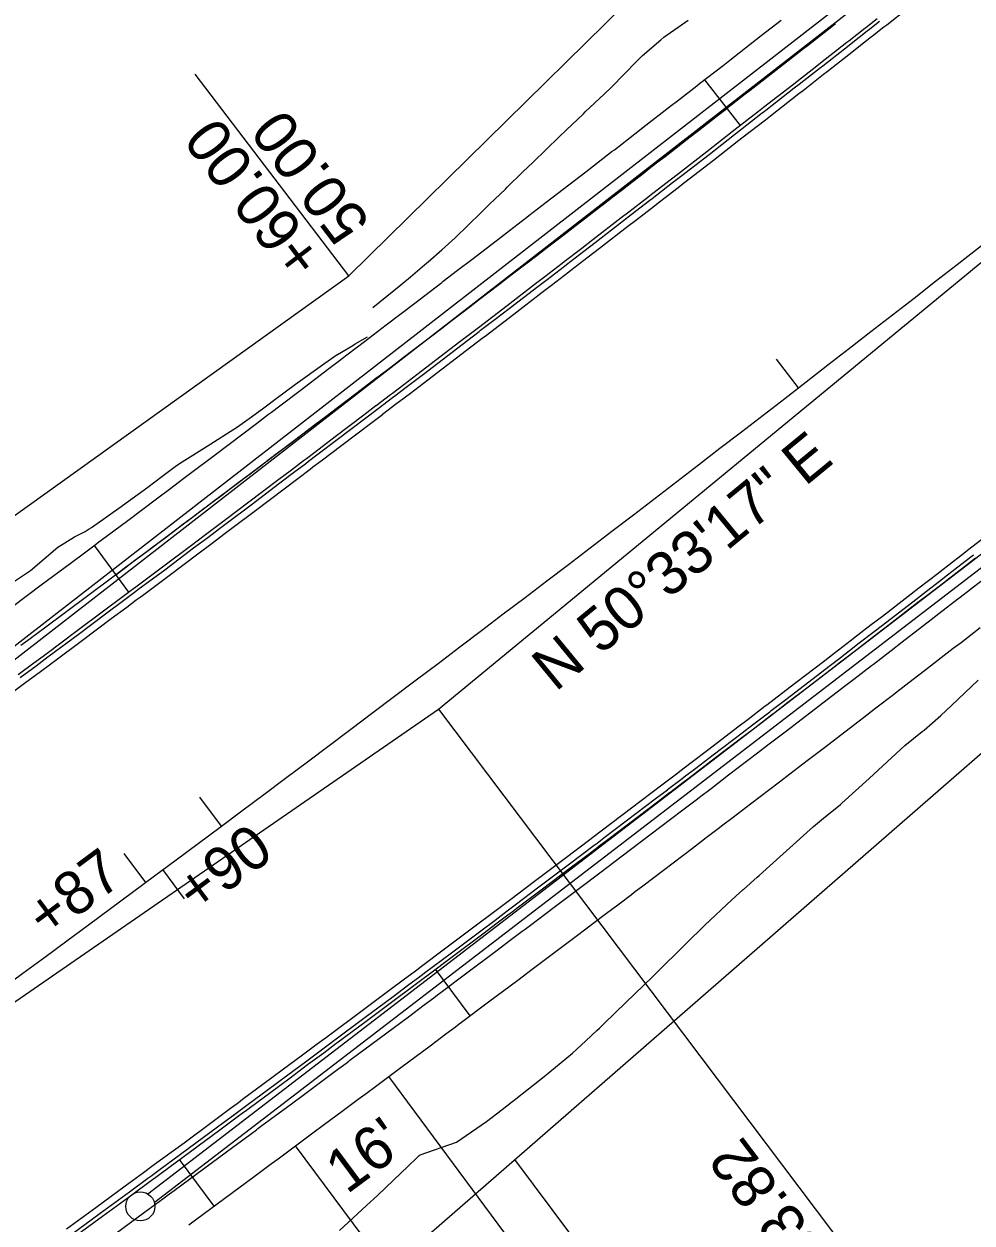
# Model space of a CAD drawing. Extents: x 1147550 to 1149124, y 2017436 to 2018779.
# Drawn here: x 1148434.3 to 1148565.1, y 2018092.6 to 2018257.9 of the extents above; entities that cross this region are included whole.
import ezdxf

# ---------------------------------------------------------------- set-up
doc = ezdxf.new("R2010")
doc.units = 0
for name, color, linetype in [('S_EDGE_CONCRETE', 7, 'Continuous'), ('S_ELECTRIC_UTILITIES', 7, 'Continuous'), ('S_HEADWALL', 7, 'Continuous'), ('S_IRON_PIN', 7, 'Continuous'), ('S_MAILBOX', 7, 'Continuous'), ('S_RDW_PT_SYM', 7, 'Continuous'), ('S_SECONDARY_CTL', 7, 'Continuous'), ('S_TELEPHONE_UTILITIES', 7, 'Continuous'), ('S_TELEPHONE_UTILITIES_ANNOT', 7, 'Continuous')]:
    doc.layers.add(name, color=color, linetype=linetype)

msp = doc.modelspace()

# ---------------------------------------------------------------- linework, layer by layer
at = {"layer": 'S_EDGE_CONCRETE'}
for p, q in [((1148491.47, 2018163.46), (1148677.53, 2018316.54)), ((1148293.22, 2018026.54), (1148491.47, 2018163.46))]:
    msp.add_line(p, q, dxfattribs=at)
for points in [[(1148538.07, 2018211.71), (1148541.13, 2018207.76)], [(1148458.49, 2018151.3), (1148461.48, 2018147.3)]]:
    msp.add_lwpolyline(points, dxfattribs=at)
msp.add_arc((1145037.29, 2022741.09), 5729.58, 304.629463, 309.445337, dxfattribs=at)
at = {"layer": 'S_ELECTRIC_UTILITIES'}
msp.add_lwpolyline([(1148479.1, 2018223.18), (1148457.89, 2018251.02)], dxfattribs=at)
at = {"layer": 'S_HEADWALL'}
for p, q in [((1148528.18, 2018250.22), (1148533.11, 2018243.93)), ((1148443.96, 2018186.01), (1148448.73, 2018179.58)), ((1148448.07, 2018143.55), (1148451.05, 2018139.54)), ((1148456.44, 2018137.31), (1148453.46, 2018141.33)), ((1148495.84, 2018121.16), (1148491.07, 2018127.58)), ((1148503.99, 2018086.7), (1148484.62, 2018112.78)), ((1148491.14, 2018077.16), (1148471.77, 2018103.24)), ((1148460.51, 2018094.93), (1148455.74, 2018101.35))]:
    msp.add_line(p, q, dxfattribs=at)
at = {"layer": 'S_IRON_PIN'}
msp.add_line((1148509.76, 2018090.99), (1148502.03, 2018101.35), dxfattribs=at)
at = {"layer": 'S_MAILBOX'}
for points in [[(1147550.1, 2017525.89), (1147894.72, 2017801.4), (1147903.55, 2017831.14), (1148035.64, 2017933.4), (1148261.5, 2018084.85), (1148285.74, 2018084.65), (1148479.1, 2018223.18), (1148835.76, 2018573.62)], [(1147623.68, 2017436.42), (1147751.67, 2017548.43), (1147958.55, 2017704.02), (1148020.45, 2017753.36), (1148124.6, 2017828.73), (1148174.25, 2017853.51), (1148282.74, 2017941.53), (1148421.63, 2018031.39), (1148612.18, 2018197.22), (1148639.91, 2018214.06), (1148753.45, 2018306.48), (1148799.03, 2018350.69)]]:
    msp.add_lwpolyline(points, dxfattribs=at)
at = {"layer": 'S_RDW_PT_SYM'}
msp.add_lwpolyline([(1148491.47, 2018163.46), (1148563.75, 2018067.67)], dxfattribs=at)
at = {"layer": 'S_SECONDARY_CTL'}
for points in [[(1148482.43, 2018218.81), (1148486.27, 2018221.95), (1148487.63, 2018223.07), (1148489.88, 2018224.99), (1148490.07, 2018225.15), (1148491.95, 2018226.8), (1148493.79, 2018228.45), (1148497.37, 2018231.94), (1148498.52, 2018233.07), (1148500.71, 2018235.17), (1148500.95, 2018235.41), (1148503.14, 2018237.52), (1148504.54, 2018238.87), (1148508.13, 2018242.35), (1148509.08, 2018243.28), (1148511.47, 2018245.54), (1148511.73, 2018245.79), (1148514.34, 2018248.24), (1148515.35, 2018249.22), (1148518.86, 2018252.79), (1148519.64, 2018253.59), (1148522.17, 2018255.76), (1148522.57, 2018256.09), (1148525.92, 2018258.43)], [(1148431.06, 2018179.8), (1148435.18, 2018182.58), (1148438.97, 2018185.79), (1148441.26, 2018187.2), (1148442.72, 2018187.96), (1148443.29, 2018188.31), (1148443.61, 2018188.5), (1148447.36, 2018191.14), (1148451.36, 2018194.08), (1148453.32, 2018195.54), (1148454.96, 2018196.75), (1148455.35, 2018197.04), (1148456.1, 2018197.53), (1148459.55, 2018199.71), (1148463.75, 2018202.38), (1148465.68, 2018203.75), (1148467.37, 2018205), (1148467.77, 2018205.29), (1148468.92, 2018206.14), (1148471.76, 2018208.24), (1148475.78, 2018211.16), (1148477.5, 2018212.33), (1148477.54, 2018212.35), (1148479.68, 2018213.61), (1148480, 2018213.8), (1148481.71, 2018214.8)], [(1148477.83, 2018091.58), (1148481.57, 2018095.01), (1148483.05, 2018096.4), (1148485.27, 2018098.5), (1148487.28, 2018100.41), (1148488.43, 2018101.52), (1148488.82, 2018101.9), (1148488.94, 2018102.01), (1148493.96, 2018103.72), (1148498.12, 2018106.58), (1148500.27, 2018108.26), (1148501.57, 2018109.27), (1148502.1, 2018109.69), (1148502.4, 2018109.92), (1148506.07, 2018112.81), (1148509.98, 2018116.01), (1148511.81, 2018117.72), (1148513.33, 2018119.15), (1148513.68, 2018119.48), (1148514.35, 2018120.12), (1148517.35, 2018123), (1148521, 2018126.55), (1148522.73, 2018128.24), (1148524.27, 2018129.75), (1148524.63, 2018130.11), (1148525.68, 2018131.14), (1148528.25, 2018133.68), (1148531.94, 2018137.17), (1148533.54, 2018138.57), (1148533.57, 2018138.59), (1148535.45, 2018140.27), (1148535.73, 2018140.52), (1148537.22, 2018141.86), (1148539.49, 2018143.9), (1148543.25, 2018147.29), (1148544.63, 2018148.44), (1148546.96, 2018150.32), (1148547.15, 2018150.49), (1148549.04, 2018152.2), (1148550.89, 2018153.89), (1148554.63, 2018157.32), (1148555.84, 2018158.42), (1148558.21, 2018160.35), (1148558.48, 2018160.57), (1148560.82, 2018162.57), (1148562.25, 2018163.94), (1148565.93, 2018167.43)]]:
    msp.add_lwpolyline(points, dxfattribs=at)
at = {"layer": 'S_TELEPHONE_UTILITIES'}
for points in [[(1148431.98, 2018165.24), (1148434.38, 2018167.02), (1148436.56, 2018168.64), (1148437.81, 2018169.57), (1148438.24, 2018169.89), (1148438.37, 2018169.98), (1148442.35, 2018172.95), (1148446.34, 2018175.93), (1148448.49, 2018177.53), (1148449.79, 2018178.5), (1148450.32, 2018178.9), (1148450.62, 2018179.12), (1148454.3, 2018181.88), (1148458.28, 2018184.87), (1148460.24, 2018186.34), (1148461.87, 2018187.57), (1148462.25, 2018187.85), (1148462.98, 2018188.4), (1148466.23, 2018190.84), (1148470.2, 2018193.84), (1148472.09, 2018195.27), (1148473.77, 2018196.54), (1148474.16, 2018196.84), (1148475.31, 2018197.7), (1148478.13, 2018199.84), (1148482.09, 2018202.84), (1148483.75, 2018204.1), (1148483.78, 2018204.13), (1148485.75, 2018205.63), (1148486.05, 2018205.85), (1148487.62, 2018207.04), (1148490, 2018208.86), (1148493.96, 2018211.87), (1148495.36, 2018212.95), (1148497.71, 2018214.74), (1148497.91, 2018214.89), (1148499.9, 2018216.41), (1148501.86, 2018217.91), (1148505.8, 2018220.94), (1148507.08, 2018221.92), (1148509.48, 2018223.76), (1148509.75, 2018223.97), (1148512.15, 2018225.82), (1148513.69, 2018227), (1148517.63, 2018230.04), (1148518.68, 2018230.85), (1148521.27, 2018232.85), (1148521.56, 2018233.07), (1148524.38, 2018235.26), (1148525.49, 2018236.12), (1148529.42, 2018239.16), (1148530.31, 2018239.85), (1148532.94, 2018241.89), (1148533.35, 2018242.21), (1148536.59, 2018244.73), (1148537.28, 2018245.26), (1148541.2, 2018248.32), (1148541.85, 2018248.82), (1148544.61, 2018250.99), (1148545.12, 2018251.38), (1148548.76, 2018254.23), (1148549.03, 2018254.44), (1148551.25, 2018256.18), (1148551.38, 2018256.28), (1148552.95, 2018257.51), (1148553.36, 2018257.83), (1148556.24, 2018260.09)], [(1148432.7, 2018177.6), (1148436.68, 2018180.57), (1148440.66, 2018183.54), (1148442.8, 2018185.14), (1148444.1, 2018186.11), (1148444.63, 2018186.51), (1148444.93, 2018186.73), (1148448.61, 2018189.48), (1148452.58, 2018192.46), (1148454.53, 2018193.93), (1148456.16, 2018195.16), (1148456.54, 2018195.44), (1148457.27, 2018195.99), (1148460.51, 2018198.43), (1148464.47, 2018201.42), (1148466.36, 2018202.85), (1148468.04, 2018204.11), (1148468.43, 2018204.41), (1148469.58, 2018205.28), (1148472.39, 2018207.41), (1148476.35, 2018210.41), (1148478.01, 2018211.67), (1148478.04, 2018211.69), (1148480, 2018213.19), (1148480.3, 2018213.41), (1148481.86, 2018214.6), (1148484.25, 2018216.42), (1148488.2, 2018219.43), (1148489.6, 2018220.5), (1148491.94, 2018222.29), (1148492.14, 2018222.44), (1148494.12, 2018223.96), (1148496.08, 2018225.46), (1148500.02, 2018228.48), (1148501.29, 2018229.45), (1148503.69, 2018231.29), (1148503.96, 2018231.5), (1148506.36, 2018233.35), (1148507.89, 2018234.53), (1148511.82, 2018237.56), (1148512.87, 2018238.37), (1148515.46, 2018240.37), (1148515.75, 2018240.59), (1148518.57, 2018242.77), (1148519.68, 2018243.63), (1148523.6, 2018246.67), (1148524.48, 2018247.35), (1148527.11, 2018249.39), (1148527.52, 2018249.71), (1148530.75, 2018252.22), (1148531.44, 2018252.76), (1148535.36, 2018255.81), (1148536, 2018256.32), (1148538.77, 2018258.47)], [(1148433.48, 2018168.22), (1148435.66, 2018169.84), (1148436.92, 2018170.77), (1148437.34, 2018171.09), (1148437.47, 2018171.19), (1148441.46, 2018174.15), (1148445.44, 2018177.13), (1148447.59, 2018178.73), (1148448.89, 2018179.7), (1148449.42, 2018180.1), (1148449.72, 2018180.33), (1148453.4, 2018183.08), (1148457.38, 2018186.07), (1148459.34, 2018187.54), (1148460.97, 2018188.77), (1148461.35, 2018189.05), (1148462.08, 2018189.6), (1148465.32, 2018192.04), (1148469.29, 2018195.03), (1148471.18, 2018196.46), (1148472.86, 2018197.73), (1148473.26, 2018198.03), (1148474.4, 2018198.9), (1148477.22, 2018201.03), (1148481.18, 2018204.04), (1148482.84, 2018205.3), (1148482.88, 2018205.32), (1148484.85, 2018206.82), (1148485.14, 2018207.04), (1148486.71, 2018208.23), (1148489.1, 2018210.05), (1148493.05, 2018213.07), (1148494.45, 2018214.14), (1148496.8, 2018215.93), (1148497, 2018216.08), (1148498.98, 2018217.6), (1148500.95, 2018219.11), (1148504.89, 2018222.13), (1148506.17, 2018223.11), (1148508.56, 2018224.95), (1148508.83, 2018225.16), (1148511.24, 2018227.01), (1148512.77, 2018228.19), (1148516.71, 2018231.22), (1148517.76, 2018232.03), (1148520.36, 2018234.04), (1148520.64, 2018234.26), (1148523.46, 2018236.44), (1148524.58, 2018237.3), (1148528.5, 2018240.35), (1148529.39, 2018241.03), (1148532.02, 2018243.08), (1148532.43, 2018243.4), (1148535.66, 2018245.91), (1148536.35, 2018246.45), (1148540.28, 2018249.5), (1148540.92, 2018250.01), (1148543.69, 2018252.17), (1148544.19, 2018252.56), (1148547.84, 2018255.41), (1148548.11, 2018255.62), (1148550.32, 2018257.36), (1148550.46, 2018257.46), (1148552.02, 2018258.69)], [(1148433.78, 2018167.82), (1148435.96, 2018169.44), (1148437.22, 2018170.37), (1148437.64, 2018170.69), (1148437.77, 2018170.78), (1148441.76, 2018173.75), (1148445.74, 2018176.73), (1148447.89, 2018178.33), (1148449.19, 2018179.3), (1148449.72, 2018179.7), (1148450.02, 2018179.93), (1148453.7, 2018182.68), (1148457.68, 2018185.67), (1148459.64, 2018187.14), (1148461.27, 2018188.37), (1148461.65, 2018188.65), (1148462.38, 2018189.2), (1148465.63, 2018191.64), (1148469.59, 2018194.64), (1148471.49, 2018196.06), (1148473.17, 2018197.33), (1148473.56, 2018197.63), (1148474.71, 2018198.5), (1148477.52, 2018200.63), (1148481.48, 2018203.64), (1148483.15, 2018204.9), (1148483.18, 2018204.92), (1148485.15, 2018206.42), (1148485.44, 2018206.64), (1148487.01, 2018207.84), (1148489.4, 2018209.66), (1148493.35, 2018212.67), (1148494.76, 2018213.74), (1148497.1, 2018215.54), (1148497.3, 2018215.69), (1148499.29, 2018217.21), (1148501.25, 2018218.71), (1148505.2, 2018221.73), (1148506.47, 2018222.71), (1148508.87, 2018224.55), (1148509.14, 2018224.76), (1148511.54, 2018226.61), (1148513.08, 2018227.79), (1148517.02, 2018230.83), (1148518.07, 2018231.64), (1148520.66, 2018233.64), (1148520.95, 2018233.87), (1148523.77, 2018236.05), (1148524.88, 2018236.91), (1148528.81, 2018239.95), (1148529.69, 2018240.64), (1148532.33, 2018242.68), (1148532.74, 2018243), (1148535.97, 2018245.52), (1148536.66, 2018246.05), (1148540.58, 2018249.11), (1148541.23, 2018249.61), (1148544, 2018251.78), (1148544.5, 2018252.17), (1148548.15, 2018255.02), (1148548.42, 2018255.23), (1148550.63, 2018256.96), (1148550.77, 2018257.07), (1148552.33, 2018258.3)], [(1148433.87, 2018172.25), (1148435.13, 2018173.18), (1148435.55, 2018173.5), (1148435.68, 2018173.59), (1148439.67, 2018176.56), (1148443.65, 2018179.53), (1148445.8, 2018181.14), (1148447.09, 2018182.11), (1148447.63, 2018182.51), (1148447.92, 2018182.73), (1148451.6, 2018185.48), (1148455.58, 2018188.46), (1148457.54, 2018189.93), (1148459.17, 2018191.16), (1148459.55, 2018191.45), (1148460.27, 2018191.99), (1148463.52, 2018194.44), (1148467.49, 2018197.43), (1148469.38, 2018198.86), (1148471.05, 2018200.13), (1148471.45, 2018200.42), (1148472.59, 2018201.29), (1148475.41, 2018203.42), (1148479.37, 2018206.42), (1148481.03, 2018207.69), (1148481.06, 2018207.71), (1148483.03, 2018209.21), (1148483.32, 2018209.43), (1148484.89, 2018210.62), (1148487.28, 2018212.44), (1148491.23, 2018215.45), (1148492.63, 2018216.52), (1148494.98, 2018218.32), (1148495.18, 2018218.47), (1148497.16, 2018219.99), (1148499.12, 2018221.49), (1148503.06, 2018224.51), (1148504.34, 2018225.49), (1148506.73, 2018227.33), (1148507, 2018227.54), (1148509.41, 2018229.38), (1148510.94, 2018230.57), (1148514.88, 2018233.6), (1148515.93, 2018234.41), (1148518.52, 2018236.41), (1148518.81, 2018236.63), (1148521.63, 2018238.81), (1148522.74, 2018239.67), (1148526.67, 2018242.72), (1148527.55, 2018243.4), (1148530.18, 2018245.45), (1148530.59, 2018245.76), (1148533.82, 2018248.28), (1148534.51, 2018248.82), (1148538.43, 2018251.87), (1148539.08, 2018252.37), (1148541.84, 2018254.53), (1148542.35, 2018254.93), (1148545.99, 2018257.77), (1148546.26, 2018257.99)], [(1148440.16, 2018091.77), (1148444.22, 2018094.74), (1148448.27, 2018097.71), (1148450.79, 2018099.56), (1148451.32, 2018099.96), (1148451.39, 2018100), (1148452.32, 2018100.69), (1148456.37, 2018103.67), (1148460.41, 2018106.66), (1148462.8, 2018108.42), (1148463.69, 2018109.08), (1148463.9, 2018109.23), (1148464.46, 2018109.65), (1148468.5, 2018112.64), (1148470.11, 2018113.84), (1148472.54, 2018115.64), (1148474.74, 2018117.28), (1148476.01, 2018118.22), (1148476.44, 2018118.54), (1148476.57, 2018118.64), (1148480.6, 2018121.64), (1148484.63, 2018124.65), (1148486.81, 2018126.27), (1148488.12, 2018127.25), (1148488.66, 2018127.66), (1148488.96, 2018127.88), (1148492.69, 2018130.67), (1148496.71, 2018133.69), (1148498.69, 2018135.17), (1148500.34, 2018136.42), (1148500.73, 2018136.71), (1148501.46, 2018137.26), (1148504.74, 2018139.73), (1148508.76, 2018142.76), (1148510.67, 2018144.2), (1148512.37, 2018145.49), (1148512.77, 2018145.79), (1148513.93, 2018146.67), (1148516.78, 2018148.82), (1148520.78, 2018151.86), (1148522.47, 2018153.14), (1148522.5, 2018153.16), (1148524.49, 2018154.68), (1148524.79, 2018154.9), (1148526.37, 2018156.11), (1148528.79, 2018157.95), (1148532.79, 2018161), (1148534.21, 2018162.08), (1148536.58, 2018163.9), (1148536.78, 2018164.05), (1148538.79, 2018165.59), (1148540.78, 2018167.11), (1148544.77, 2018170.17), (1148546.06, 2018171.16), (1148548.48, 2018173.02), (1148548.75, 2018173.23), (1148551.18, 2018175.1), (1148552.74, 2018176.29), (1148556.72, 2018179.36), (1148557.78, 2018180.18), (1148560.41, 2018182.21), (1148560.7, 2018182.44), (1148563.55, 2018184.64), (1148564.68, 2018185.51), (1148568.65, 2018188.59)], [(1148440.75, 2018090.96), (1148444.81, 2018093.93), (1148448.86, 2018096.91), (1148451.38, 2018098.76), (1148451.92, 2018099.15), (1148451.98, 2018099.2), (1148452.91, 2018099.89), (1148456.96, 2018102.87), (1148461.01, 2018105.85), (1148463.4, 2018107.62), (1148464.29, 2018108.28), (1148464.49, 2018108.43), (1148465.05, 2018108.84), (1148469.09, 2018111.84), (1148470.71, 2018113.03), (1148473.13, 2018114.83), (1148475.34, 2018116.47), (1148476.61, 2018117.42), (1148477.04, 2018117.74), (1148477.17, 2018117.83), (1148481.2, 2018120.84), (1148485.23, 2018123.84), (1148487.41, 2018125.47), (1148488.72, 2018126.45), (1148489.26, 2018126.85), (1148489.56, 2018127.08), (1148493.29, 2018129.87), (1148497.31, 2018132.89), (1148499.29, 2018134.37), (1148500.94, 2018135.62), (1148501.33, 2018135.91), (1148502.06, 2018136.46), (1148505.35, 2018138.93), (1148509.36, 2018141.96), (1148511.27, 2018143.41), (1148512.97, 2018144.69), (1148513.37, 2018144.99), (1148514.53, 2018145.87), (1148517.38, 2018148.03), (1148521.39, 2018151.07), (1148523.07, 2018152.34), (1148523.1, 2018152.37), (1148525.1, 2018153.88), (1148525.39, 2018154.11), (1148526.98, 2018155.31), (1148529.39, 2018157.15), (1148533.39, 2018160.2), (1148534.81, 2018161.29), (1148537.19, 2018163.1), (1148537.39, 2018163.26), (1148539.4, 2018164.79), (1148541.38, 2018166.31), (1148545.37, 2018169.37), (1148546.66, 2018170.36), (1148549.09, 2018172.22), (1148549.36, 2018172.44), (1148551.79, 2018174.31), (1148553.35, 2018175.5), (1148557.33, 2018178.57), (1148558.39, 2018179.39), (1148561.02, 2018181.42), (1148561.31, 2018181.65), (1148564.16, 2018183.85), (1148565.29, 2018184.72)], [(1148441.05, 2018090.56), (1148445.1, 2018093.53), (1148449.16, 2018096.5), (1148451.68, 2018098.35), (1148452.21, 2018098.75), (1148452.28, 2018098.8), (1148453.21, 2018099.48), (1148457.26, 2018102.47), (1148461.31, 2018105.45), (1148463.69, 2018107.22), (1148464.58, 2018107.88), (1148464.79, 2018108.03), (1148465.35, 2018108.44), (1148469.39, 2018111.44), (1148471.01, 2018112.63), (1148473.43, 2018114.43), (1148475.64, 2018116.07), (1148476.91, 2018117.01), (1148477.34, 2018117.34), (1148477.47, 2018117.43), (1148481.5, 2018120.44), (1148485.53, 2018123.44), (1148487.71, 2018125.07), (1148489.02, 2018126.05), (1148489.56, 2018126.45), (1148489.86, 2018126.68), (1148493.59, 2018129.47), (1148497.61, 2018132.49), (1148499.59, 2018133.98), (1148501.24, 2018135.22), (1148501.63, 2018135.51), (1148502.36, 2018136.06), (1148505.65, 2018138.53), (1148509.66, 2018141.56), (1148511.58, 2018143.01), (1148513.27, 2018144.29), (1148513.67, 2018144.59), (1148514.83, 2018145.47), (1148517.68, 2018147.63), (1148521.69, 2018150.67), (1148523.37, 2018151.95), (1148523.41, 2018151.97), (1148525.4, 2018153.48), (1148525.7, 2018153.71), (1148527.28, 2018154.92), (1148529.7, 2018156.76), (1148533.7, 2018159.81), (1148535.12, 2018160.89), (1148537.49, 2018162.71), (1148537.69, 2018162.86), (1148539.7, 2018164.4), (1148541.69, 2018165.92), (1148545.68, 2018168.98), (1148546.97, 2018169.97), (1148549.39, 2018171.83), (1148549.67, 2018172.04), (1148552.1, 2018173.91), (1148553.65, 2018175.11), (1148557.64, 2018178.18), (1148558.7, 2018179), (1148561.33, 2018181.02), (1148561.62, 2018181.25), (1148564.47, 2018183.46), (1148565.59, 2018184.33)], [(1148446.88, 2018091.11), (1148450.93, 2018094.09), (1148453.45, 2018095.94), (1148453.99, 2018096.33), (1148454.05, 2018096.38), (1148454.99, 2018097.07), (1148459.04, 2018100.05), (1148463.09, 2018103.04), (1148465.48, 2018104.8), (1148466.37, 2018105.46), (1148466.57, 2018105.61), (1148467.13, 2018106.03), (1148471.18, 2018109.03), (1148472.79, 2018110.22), (1148475.22, 2018112.02), (1148477.43, 2018113.66), (1148478.7, 2018114.61), (1148479.13, 2018114.93), (1148479.26, 2018115.03), (1148483.29, 2018118.03), (1148487.33, 2018121.04), (1148489.5, 2018122.67), (1148490.82, 2018123.65), (1148491.36, 2018124.05), (1148491.66, 2018124.28), (1148495.38, 2018127.07), (1148499.41, 2018130.09), (1148501.39, 2018131.58), (1148503.05, 2018132.82), (1148503.43, 2018133.11), (1148504.16, 2018133.66), (1148507.45, 2018136.14), (1148511.47, 2018139.17), (1148513.38, 2018140.61), (1148515.08, 2018141.9), (1148515.48, 2018142.2), (1148516.64, 2018143.08), (1148519.5, 2018145.24), (1148523.5, 2018148.28), (1148525.19, 2018149.56), (1148525.22, 2018149.58), (1148527.21, 2018151.1), (1148527.51, 2018151.32), (1148529.1, 2018152.53), (1148531.52, 2018154.37), (1148535.52, 2018157.42), (1148536.94, 2018158.51), (1148539.32, 2018160.32), (1148539.52, 2018160.48), (1148541.53, 2018162.01), (1148543.51, 2018163.53), (1148547.51, 2018166.6), (1148548.8, 2018167.59), (1148551.22, 2018169.45), (1148551.5, 2018169.66), (1148553.93, 2018171.53), (1148555.48, 2018172.73), (1148559.47, 2018175.8), (1148560.53, 2018176.62), (1148563.16, 2018178.65), (1148563.45, 2018178.88), (1148566.31, 2018181.08)], [(1148457.02, 2018092.35), (1148457.95, 2018093.04), (1148462.01, 2018096.03), (1148466.06, 2018099.02), (1148468.45, 2018100.78), (1148469.34, 2018101.44), (1148469.55, 2018101.59), (1148470.11, 2018102.01), (1148474.16, 2018105.01), (1148475.77, 2018106.21), (1148478.2, 2018108.01), (1148480.41, 2018109.65), (1148481.68, 2018110.6), (1148482.11, 2018110.92), (1148482.24, 2018111.01), (1148486.28, 2018114.02), (1148490.32, 2018117.03), (1148492.5, 2018118.66), (1148493.81, 2018119.64), (1148494.35, 2018120.05), (1148494.65, 2018120.27), (1148498.38, 2018123.07), (1148502.41, 2018126.09), (1148504.4, 2018127.58), (1148506.05, 2018128.82), (1148506.44, 2018129.12), (1148507.17, 2018129.67), (1148510.46, 2018132.14), (1148514.48, 2018135.18), (1148516.4, 2018136.62), (1148518.1, 2018137.91), (1148518.5, 2018138.21), (1148519.66, 2018139.09), (1148522.52, 2018141.25), (1148526.53, 2018144.3), (1148528.21, 2018145.57), (1148528.24, 2018145.6), (1148530.24, 2018147.12), (1148530.54, 2018147.34), (1148532.13, 2018148.55), (1148534.55, 2018150.39), (1148538.55, 2018153.45), (1148539.97, 2018154.53), (1148542.35, 2018156.35), (1148542.55, 2018156.5), (1148544.56, 2018158.04), (1148546.55, 2018159.56), (1148550.55, 2018162.63), (1148551.84, 2018163.62), (1148554.27, 2018165.48), (1148554.54, 2018165.7), (1148556.98, 2018167.57), (1148558.53, 2018168.77), (1148562.52, 2018171.84), (1148563.59, 2018172.66), (1148566.22, 2018174.69)]]:
    msp.add_lwpolyline(points, dxfattribs=at)
msp.add_arc((1145037.29, 2022741.09), 5693.08, 306.79204, 307.85922, dxfattribs=at)
at = {"layer": 'S_TELEPHONE_UTILITIES_ANNOT'}
for p, q in [((1148409.31, 2018153.84), (1148641.93, 2018334.28)), ((1148409.31, 2018153.84), (1148641.93, 2018334.28)), ((1148410.23, 2018152.66), (1148642.85, 2018333.1)), ((1148410.23, 2018152.66), (1148642.85, 2018333.1)), ((1148451.36, 2018096.62), (1148639.98, 2018241.36)), ((1148451.36, 2018096.62), (1148639.98, 2018241.36)), ((1148452.27, 2018095.43), (1148640.9, 2018240.17)), ((1148452.27, 2018095.43), (1148640.9, 2018240.17))]:
    msp.add_line(p, q, dxfattribs=at)
msp.add_circle((1148450.34, 2018094.89), 2, dxfattribs=at)

# ---------------------------------------------------------------- texts
at = {"layer": 'S_ELECTRIC_UTILITIES'}
for s, p in [('50.00', (1148482.24, 2018230.6)), ('+60.00', (1148475.88, 2018225.75))]:
    msp.add_text(s, height=6, rotation=127.3006, dxfattribs=at).set_placement(p)
at = {"layer": 'S_HEADWALL'}
for s, rotation, p in [('+90', 36.6006, (1148458.11, 2018135.06)), ('+87', 36.5706, (1148437.43, 2018131.67)), ("16'", 36.6006, (1148478.84, 2018096.48))]:
    msp.add_text(s, height=6, rotation=rotation, dxfattribs=at).set_placement(p)
at = {"layer": 'S_RDW_PT_SYM'}
for s, rotation, p in [('N 50%%d33\'17" E', 39.4453, (1148507.62, 2018165.74)), ('P.I. 52+33.82', 127.0374, (1148562.15, 2018066.47))]:
    msp.add_text(s, height=6, rotation=rotation, dxfattribs=at).set_placement(p)

doc.saveas('drawing.dxf')
